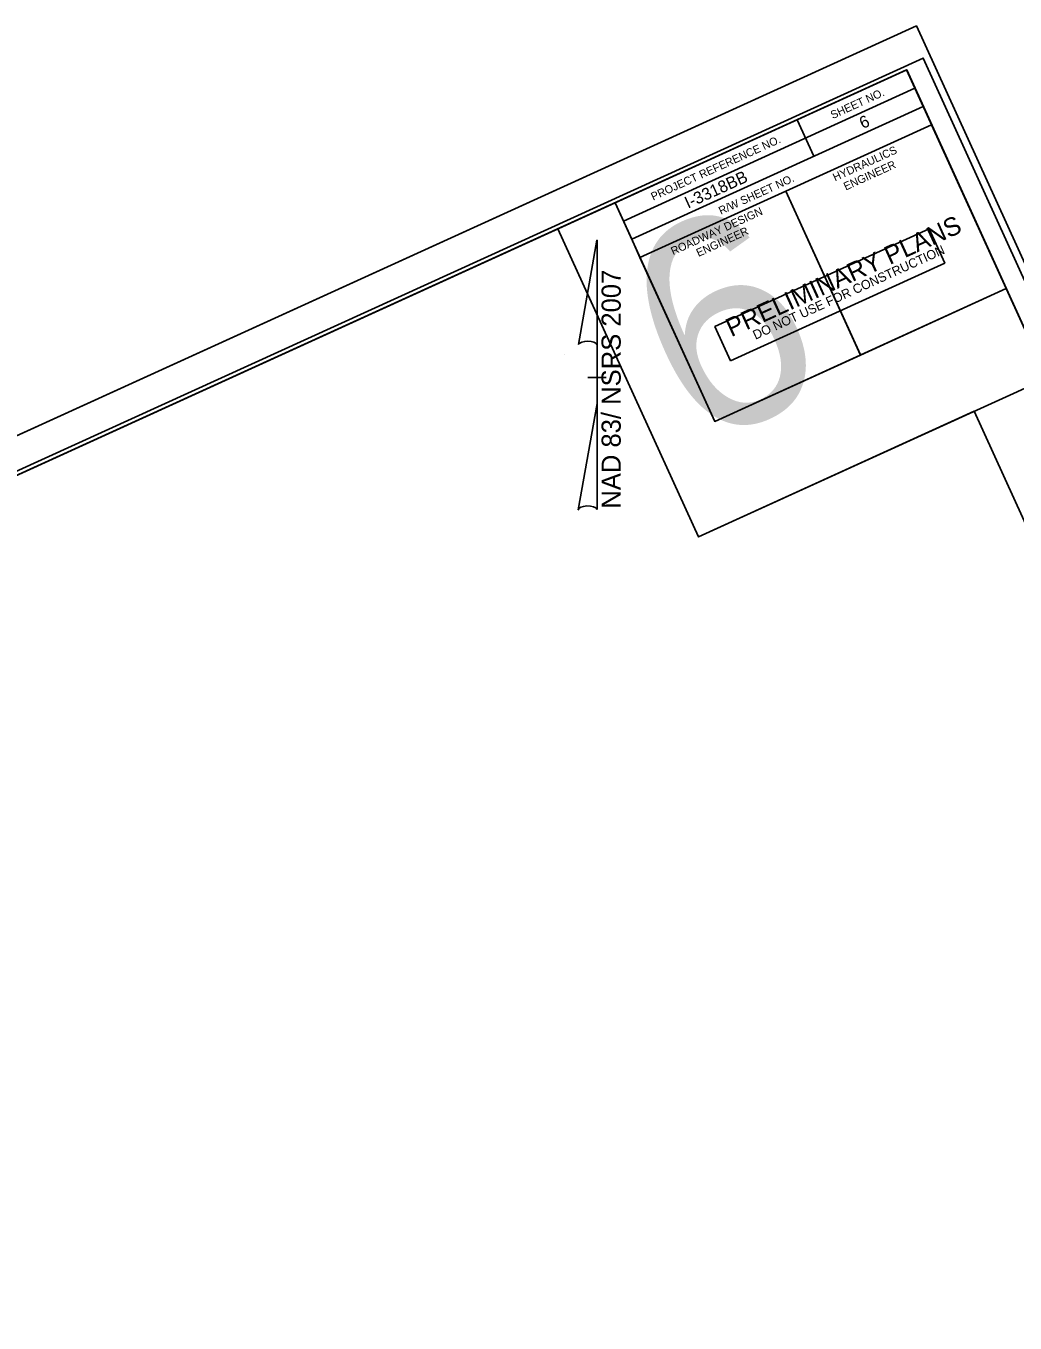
# Model space of a CAD drawing. Extents: x 2249019 to 2251039, y 663030 to 664799.
# Drawn here: x 2250029 to 2250647, y 663915 to 664725 of the extents above; entities that cross this region are included whole.
import ezdxf

# ---------------------------------------------------------------- set-up
doc = ezdxf.new("R2010")
doc.units = 0
for name, color, linetype in [('Prop North Arrow NAD83 for Plan Sheets CELL', 7, 'Continuous'), ('Sheet Clip Boundary CELL', 7, 'Continuous'), ('Sheet Cutting Line CELL', 7, 'Continuous'), ('Sheet Data Field CELL', 7, 'Continuous'), ('Sheet Layout Plan Border', 7, 'Continuous'), ('Sheet North Arrow Point CELL', 7, 'Continuous'), ('Sheet Plan CELL', 7, 'Continuous'), ('Sheet Plan Layout CELL', 7, 'Continuous'), ('Sheet Plot Border Inside CELL', 7, 'Continuous'), ('Sheet Plot Border Outside CELL', 7, 'Continuous'), ('Sheet Sticker Preliminary CELL', 7, 'Continuous')]:
    doc.layers.add(name, color=color, linetype=linetype)

msp = doc.modelspace()

# ---------------------------------------------------------------- linework, layer by layer
at = {"layer": 'Prop North Arrow NAD83 for Plan Sheets CELL'}
for p, q in [((2250373.96, 664525.91), (2250385.49, 664591.09)), ((2250385.56, 664591.09), (2250385.49, 664591.09)), ((2250385.56, 664591.09), (2250385.49, 664591.09)), ((2250385.56, 664591.09), (2250385.56, 664523.88)), ((2250385.56, 664489), (2250385.56, 664525.84)), ((2250385.56, 664523.88), (2250385.56, 664525.77)), ((2250379.94, 664505.31), (2250379.87, 664505.31)), ((2250384.93, 664505.31), (2250379.94, 664505.31)), ((2250380.01, 664505.31), (2250391.26, 664505.31)), ((2250385.56, 664489), (2250373.82, 664422.56)), ((2250385.63, 664422.84), (2250385.56, 664489))]:
    msp.add_line(p, q, dxfattribs=at)
for centre, start_param, end_param in [((2250379.78, 664525.22), 0.216388, 2.908219), ((2250379.78, 664422.32), 0.201328, 3.141593)]:
    msp.add_ellipse(centre, major_axis=(5.95, -0.04), ratio=0.461098, start_param=start_param, end_param=end_param, dxfattribs=at)
at = {"layer": 'Sheet Clip Boundary CELL'}
msp.add_lwpolyline([(2249425.27, 663908.72), (2249673.42, 663362.44), (2249790.02, 663300.88), (2249798.45, 663191.7), (2249694.77, 663140.6), (2250968.75, 663721.13), (2250621.05, 664484.16), (2250448.83, 664405.68), (2250361.13, 664598.13), (2249259.38, 664096.08)], close=True, dxfattribs=at)
at = {"layer": 'Sheet Cutting Line CELL'}
msp.add_line((2250585, 664724.85), (2249053.06, 664026.77), dxfattribs=at)
at = {"layer": 'Sheet Layout Plan Border'}
msp.add_lwpolyline([(2249694.77, 663140.6), (2250968.75, 663721.13), (2250621.05, 664484.16), (2250448.83, 664405.68), (2250361.13, 664598.13), (2249259.38, 664096.08)], close=True, dxfattribs=at)
at = {"layer": 'Sheet North Arrow Point CELL'}
msp.add_line((2250365.12, 664519.79), (2250365.12, 664519.79), dxfattribs=at)
at = {"layer": 'Sheet Plan CELL'}
for p, q in [((2250402, 664602.97), (2250584.05, 664685.92)), ((2250407.21, 664591.57), (2250589.23, 664674.54)), ((2250407.21, 664591.57), (2250589.23, 664674.54)), ((2250510.6, 664666.17), (2250521.01, 664643.44)), ((2250503.43, 664621.69), (2250550.08, 664519.36)), ((2250407.21, 664591.57), (2250412.39, 664580.21))]:
    msp.add_line(p, q, dxfattribs=at)
for points in [[(2250578.88, 664697.35), (2249213.88, 664075.35), (2249649.27, 663119.87), (2251014.25, 663741.87)], [(2250396.81, 664614.4), (2250578.88, 664697.35), (2250589.23, 664674.54), (2250407.21, 664591.57)], [(2250503.43, 664621.69), (2250594.42, 664663.17), (2250641.08, 664560.79), (2250550.09, 664519.31)], [(2249649.27, 663119.87), (2249213.87, 664075.31), (2250396.81, 664614.4), (2250459.05, 664477.85), (2250641.08, 664560.79), (2251014.25, 663741.87)], [(2250412.39, 664580.21), (2250503.43, 664621.69), (2250550.09, 664519.31), (2250459.05, 664477.85)]]:
    msp.add_lwpolyline(points, close=True, dxfattribs=at)
at = {"layer": 'Sheet Plan Layout CELL'}
for points in [[(2250448.83, 664405.68), (2250666.56, 664504.9), (2250578.89, 664697.36), (2250361.13, 664598.13)], [(2249213.87, 664075.31), (2249649.27, 663119.87), (2251014.24, 663741.86), (2250666.54, 664504.89), (2250448.83, 664405.68), (2250361.13, 664598.13)]]:
    msp.add_lwpolyline(points, close=True, dxfattribs=at)
at = {"layer": 'Sheet Plot Border Inside CELL'}
msp.add_lwpolyline([(2249510.65, 663053.94), (2251026.65, 663744.77), (2250589.2, 664704.79), (2249073.18, 664013.96)], close=True, dxfattribs=at)
at = {"layer": 'Sheet Plot Border Outside CELL'}
msp.add_lwpolyline([(2249507.11, 663030.35), (2251039.05, 663728.43), (2250585, 664724.85), (2249053.06, 664026.77)], close=True, dxfattribs=at)
at = {"layer": 'Sheet Sticker Preliminary CELL'}
msp.add_lwpolyline([(2250468.89, 664515.72), (2250459.15, 664537.11), (2250592.91, 664598.06), (2250602.66, 664576.68)], close=True, dxfattribs=at)

# ---------------------------------------------------------------- texts
at = {"layer": 'Prop North Arrow NAD83 for Plan Sheets CELL'}
msp.add_text('NAD 83/ NSRS 2007', height=11.9532, rotation=90, dxfattribs=at).set_placement((2250400.36, 664423.33))
at = {"layer": 'Sheet Data Field CELL'}
for s, p in [('6', (2250551.47, 664660.41)), ('I-3318BB', (2250442.35, 664610.62))]:
    msp.add_text(s, height=7.5, rotation=24.49795, dxfattribs=at).set_placement(p)
at = {"layer": 'Sheet Plan CELL'}
for s, height, p in [('SHEET NO.', 5, (2250532.75, 664666.63)), ('PROJECT REFERENCE NO.', 5.0001, (2250420.63, 664615.67)), ('HYDRAULICS', 5, (2250534.17, 664627.71)), ('ENGINEER', 5, (2250540.9, 664622.02)), ('R/W SHEET NO.', 5.0001, (2250462.89, 664606.85)), ('ROADWAY DESIGN', 5.0001, (2250433.05, 664581.6)), ('ENGINEER', 5, (2250448.9, 664580.54))]:
    msp.add_text(s, height=height, rotation=24.49795, dxfattribs=at).set_placement(p)
at = {"layer": 'Sheet Plan Layout CELL'}
msp.add_text('6 ', height=131.25, rotation=24.49794, dxfattribs=at).set_placement((2250446.27, 664459.92))
at = {"layer": 'Sheet Sticker Preliminary CELL'}
for s, height, p in [('PRELIMINARY PLANS', 11.52, (2250469.35, 664530.39)), ('DO NOT USE FOR CONSTRUCTION', 5.76, (2250484.47, 664528.81))]:
    msp.add_text(s, height=height, rotation=24.49794, dxfattribs=at).set_placement(p)

doc.saveas('drawing.dxf')
